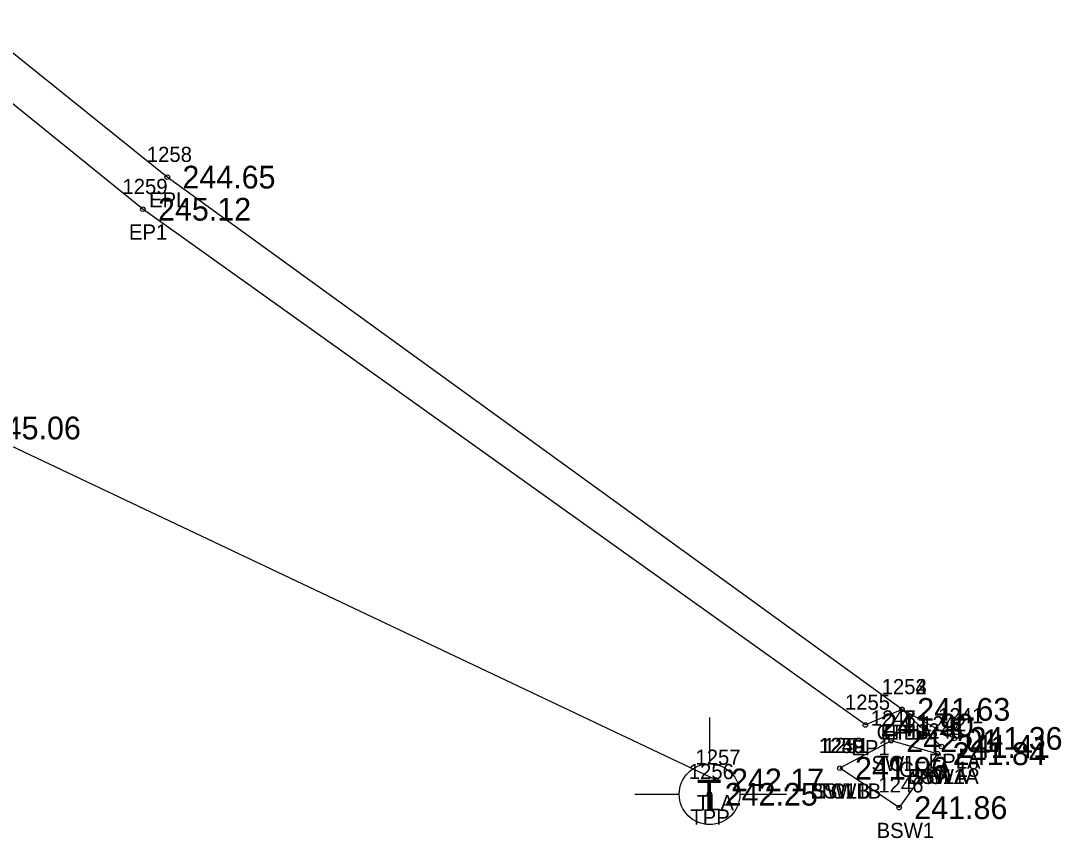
# Model space of a CAD drawing. Extents: x 1961231 to 1962574, y 799865 to 801120.
# Drawn here: x 1962180.3 to 1962248.8, y 800309.1 to 800363 of the extents above; entities that cross this region are included whole.
import ezdxf

# ---------------------------------------------------------------- set-up
doc = ezdxf.new("R2010")
doc.units = 0
for name, color, linetype in [('RD_EX_Conc', 7, 'Continuous'), ('RD_EX_Conc_txCode', 7, 'Continuous'), ('RD_EX_Road', 7, 'Continuous'), ('RD_EX_Road_txCode', 7, 'Continuous'), ('RD_EX_TX_Conc_ELEV', 7, 'Continuous'), ('RD_EX_TX_Road_ELEV', 7, 'Continuous'), ('RD_EX_TX_UT_ELEV', 7, 'Continuous'), ('RD_EX_TX_VEG_ELEV', 7, 'Continuous'), ('RD_EX_UT', 7, 'Continuous'), ('RD_EX_UT_txCode', 7, 'Continuous'), ('RD_EX_VEG', 7, 'Continuous'), ('RD_EX_VEG_txCode', 7, 'Continuous'), ('RD_SMD_Locator', 7, 'Continuous')]:
    doc.layers.add(name, color=color, linetype=linetype)

msp = doc.modelspace()

# ---------------------------------------------------------------- linework, layer by layer
at = {"layer": 'RD_EX_Conc'}
msp.add_line((1962240.955, 800315.148), (1962238.351, 800317.597), dxfattribs=at)
for points in [[(1962240.69, 800314.676), (1962237.631, 800315.532), (1962234.25, 800313.717)], [(1962240.69, 800314.676), (1962238.157, 800311.117), (1962234.25, 800313.717)]]:
    msp.add_lwpolyline(points, dxfattribs=at)
at = {"layer": 'RD_EX_Road'}
for points in [[(1962241.795, 800315.68), (1962238.351, 800317.597), (1962189.917, 800352.695), (1962151.637, 800383.489), (1962113.782, 800416.386), (1962074.109, 800451.288), (1962034.784, 800486.956), (1962017.07, 800503.174), (1961999.461, 800519.248), (1961962.476, 800552.117), (1961937.077, 800573.106), (1961923.189, 800584.904), (1961883.072, 800617.432), (1961838.294, 800653.432), (1961801.423, 800682.572), (1961728.409, 800740.856), (1961722.948, 800745.107), (1961689.132, 800771.929)], [(1962238.351, 800317.597), (1962235.932, 800316.569), (1962188.31, 800350.578), (1962150.215, 800381.436), (1962111.822, 800414.885), (1962080.072, 800442.592), (1962070.813, 800442.862), (1962050.611, 800440.1), (1962031.046, 800427.323), (1962017.916, 800411.541)]]:
    msp.add_lwpolyline(points, dxfattribs=at)
at = {"layer": 'RD_EX_UT'}
for p, q in [((1962225.663, 800317.071), (1962225.663, 800314.001)), ((1962220.732, 800312.017), (1962223.663, 800312.017)), ((1962227.663, 800312.017), (1962230.732, 800312.017))]:
    msp.add_line(p, q, dxfattribs=at)
msp.add_circle((1962225.663, 800312.001), 2, dxfattribs=at)
at = {"layer": 'RD_EX_VEG'}
msp.add_lwpolyline([(1962226.079, 800312.945), (1962177.086, 800336.152), (1962133.392, 800353.37), (1962121.982, 800335.416)], dxfattribs=at)
at = {"layer": 'RD_SMD_Locator'}
for centre in [(1962189.917, 800352.695), (1962188.31, 800350.578), (1962238.351, 800317.597), (1962238.351, 800317.597), (1962238.351, 800317.597), (1962235.932, 800316.569), (1962241.795, 800315.68), (1962237.631, 800315.532), (1962237.631, 800315.532), (1962240.955, 800315.148), (1962240.69, 800314.676), (1962240.69, 800314.676), (1962240.69, 800314.676), (1962234.25, 800313.717), (1962234.25, 800313.717), (1962234.25, 800313.717), (1962226.079, 800312.945), (1962225.663, 800312.001), (1962238.157, 800311.117)]:
    msp.add_circle(centre, 0.15, dxfattribs=at)

# ---------------------------------------------------------------- texts
at = {"layer": 'RD_EX_Conc_txCode'}
for s, p in [('1252', (1962237.005, 800318.597)), ('1247', (1962236.285, 800316.532)), ('1248', (1962236.285, 800316.532)), ('CFLB', (1962236.674, 800315.597)), ('1243', (1962239.343, 800315.676)), ('1244', (1962239.343, 800315.676)), ('1245', (1962239.343, 800315.676)), ('1242', (1962239.609, 800316.148)), ('1250', (1962232.864, 800314.717)), ('1249', (1962232.903, 800314.717)), ('1251', (1962233.187, 800314.717)), ('SWL', (1962236.34, 800313.532)), ('TC1', (1962236.67, 800313.532)), ('CFLA 18', (1962238.16, 800313.148)), ('1246', (1962236.787, 800312.117)), ('BSW1A', (1962238.721, 800312.676)), ('SWLA', (1962238.91, 800312.676)), ('TC1A', (1962239.241, 800312.676)), ('BSW1B', (1962232.297, 800311.717)), ('SWLB', (1962232.486, 800311.717)), ('TC1B', (1962232.817, 800311.717)), ('BSW1', (1962236.677, 800309.117))]:
    msp.add_text(s, height=1, dxfattribs=at).set_placement(p)
at = {"layer": 'RD_EX_Road_txCode'}
for s, p in [('1258', (1962188.571, 800353.695)), ('1259', (1962186.963, 800351.578)), ('EPL', (1962188.713, 800350.695)), ('EP1', (1962187.388, 800348.578)), ('1253', (1962237.005, 800318.597)), ('1254', (1962237.005, 800318.597)), ('1255', (1962234.585, 800317.569)), ('1241', (1962240.732, 800316.68)), ('EP1A', (1962236.942, 800315.597)), ('EPL', (1962237.146, 800315.597)), ('EP1', (1962235.011, 800314.569)), ('EPLA', (1962240.102, 800313.68))]:
    msp.add_text(s, height=1, dxfattribs=at).set_placement(p)
at = {"layer": 'RD_EX_TX_Conc_ELEV'}
for s, p in [('241.63', (1962239.351, 800316.847)), ('242.01', (1962238.631, 800314.782)), ('242.01', (1962238.631, 800314.782)), ('241.41', (1962241.955, 800314.398)), ('241.84', (1962241.69, 800313.926)), ('241.84', (1962241.69, 800313.926)), ('241.84', (1962241.69, 800313.926)), ('241.96', (1962235.25, 800312.967)), ('241.96', (1962235.25, 800312.967)), ('241.96', (1962235.25, 800312.967)), ('241.86', (1962239.157, 800310.367))]:
    msp.add_text(s, height=1.5, dxfattribs=at).set_placement(p)
at = {"layer": 'RD_EX_TX_Road_ELEV'}
for s, p in [('244.65', (1962190.917, 800351.945)), ('245.12', (1962189.31, 800349.828)), ('241.63', (1962239.351, 800316.847)), ('241.63', (1962239.351, 800316.847)), ('241.90', (1962236.932, 800315.819)), ('241.36', (1962242.795, 800314.93))]:
    msp.add_text(s, height=1.5, dxfattribs=at).set_placement(p)
at = {"layer": 'RD_EX_TX_UT_ELEV'}
msp.add_text('242.25', height=1.5, dxfattribs=at).set_placement((1962226.663, 800311.251))
at = {"layer": 'RD_EX_TX_VEG_ELEV'}
for s, p in [('245.06', (1962178.086, 800335.402)), ('242.17', (1962227.079, 800312.195))]:
    msp.add_text(s, height=1.5, dxfattribs=at).set_placement(p)
at = {"layer": 'RD_EX_UT'}
msp.add_text('T', height=2, dxfattribs=at).set_placement((1962224.814, 800310.954))
at = {"layer": 'RD_EX_UT_txCode'}
for s, p in [('1256', (1962224.293, 800313.001)), ('TPP', (1962224.395, 800310.001))]:
    msp.add_text(s, height=1, dxfattribs=at).set_placement(p)
at = {"layer": 'RD_EX_VEG_txCode'}
for s, p in [('1257', (1962224.732, 800313.945)), ('TLA', (1962224.819, 800310.945))]:
    msp.add_text(s, height=1, dxfattribs=at).set_placement(p)

doc.saveas('drawing.dxf')
